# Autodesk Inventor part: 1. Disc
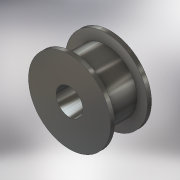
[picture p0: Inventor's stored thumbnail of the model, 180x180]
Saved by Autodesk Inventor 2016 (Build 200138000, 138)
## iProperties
Created: 2016-01
Part Number: 1. Disc
Material: Generic
Document SubType Name: Modeling
Designer: Black Falcon
Density: 1 g/cm^3
Appearance: Chrome - Polished
Author: Black Falcon
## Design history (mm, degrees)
sketch "Sketch1"
  geometry: C1 r 16.675 at (0, 0); C2 r 38.1 at (0, 0); 1 further point
  constraints: 2 centre point, 2 coincident
  dimensions: "d0" = 33.3502 diameter of C1; "d1" = 76.2 diameter of C2
extrude "Extrusion1" new body sketch "Sketch1" distance "d2" = 50.8; taper "d3" = 0 deg
sketch "Sketch2"
  geometry: C1 r 50.8 at (0, 0); C2 r 38.1 at (0, 0) reference; 1 further point
  constraints: 1 centre point, 1 coincident
  dimensions: "d4" = 101.6 diameter of C1
extrude "Extrusion2" join sketch "Sketch2" distance "d5" = 5.08; taper "d6" = 0 deg
workplane "Work Plane1"
mirror "Mirror1"
body "Solid1"
